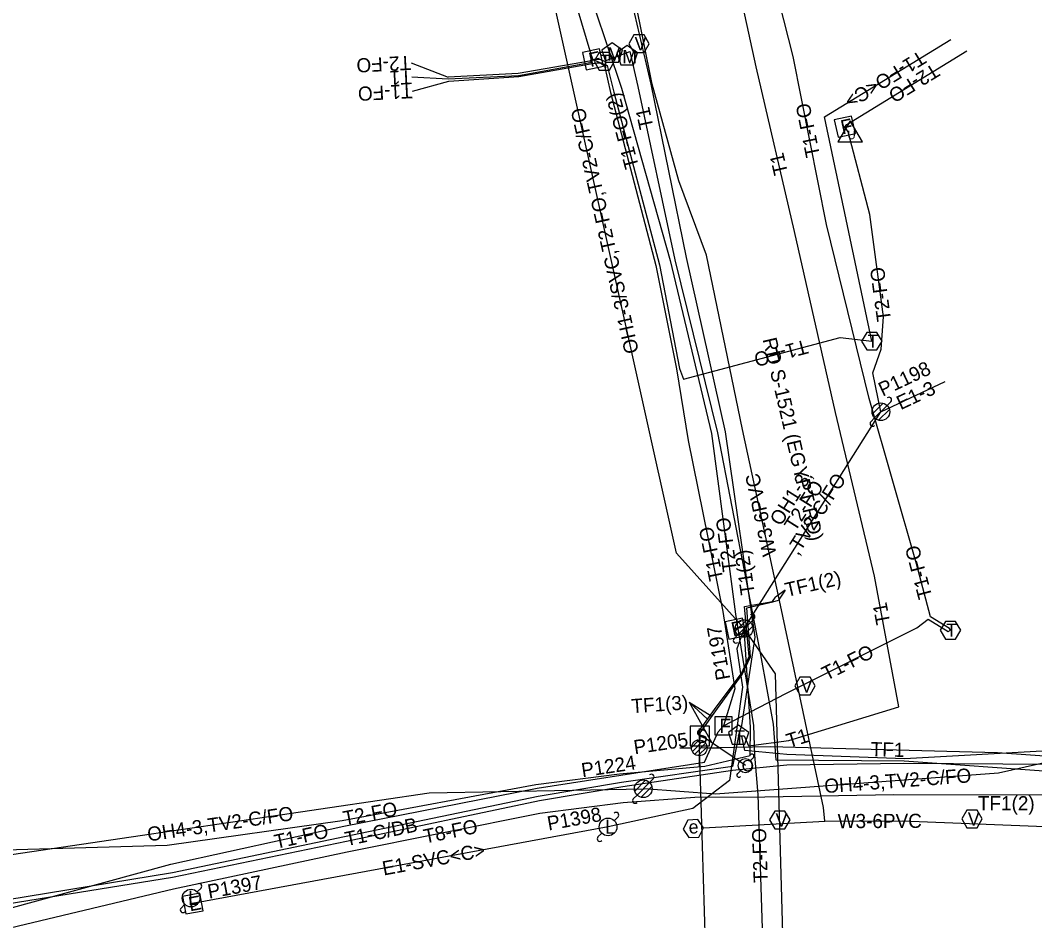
# Model space of a CAD drawing. Extents: x 2336688 to 2352634, y 362473 to 369571.
# Drawn here: x 2351896.3 to 2352182.9, y 368960.9 to 369215.5 of the extents above; entities that cross this region are included whole.
import ezdxf

# ---------------------------------------------------------------- set-up
doc = ezdxf.new("R2010")
doc.units = 0
for name, color, linetype in [('RD_EX_DV_Prop', 7, 'Continuous'), ('RD_EX_DV_TX_Prop', 7, 'Continuous'), ('RD_EX_RW', 7, 'Continuous'), ('RD_EX_RW_TX', 7, 'Continuous'), ('RD_HC_Data_Tic', 7, 'Continuous'), ('RD_PD_CstnLmt', 7, 'Continuous'), ('RD_PD_Final_TrvlWay', 7, 'Continuous'), ('RD_PD_FOC', 7, 'Continuous'), ('RD_PD_PatLn3', 7, 'Continuous'), ('RD_PD_PatLn4', 7, 'Continuous'), ('RD_SHT_ShtClip', 7, 'Continuous'), ('RD_Sketch2', 7, 'Continuous'), ('RD_Sketch8', 7, 'Continuous'), ('RD_TX_Misc1', 7, 'Continuous')]:
    doc.layers.add(name, color=color, linetype=linetype)

msp = doc.modelspace()

# ---------------------------------------------------------------- linework, layer by layer
at = {"layer": 'RD_EX_RW'}
for p, q in [((2352006.73, 369203.5), (2352017.18, 369199.37)), ((2352006.94, 369199.47), (2352017.22, 369198.89)), ((2352007.11, 369195.47), (2352017.4, 369198.31))]:
    msp.add_line(p, q, dxfattribs=at)
at = {"layer": 'RD_EX_RW_TX'}
for points in [[(2351882.96, 368961.6), (2351938.79, 368976.9), (2351987.72, 368987.57), (2352042.33, 368998.31), (2352089.62, 369005.75), (2352093.46, 369014.31), (2352094.98, 369015.98), (2352112.55, 369025.15), (2352149.58, 369043.65), (2352152.79, 369046.13), (2352158.47, 369042.65), (2352159.12, 369043.02), (2352158.82, 369043.5), (2352153.46, 369046.79), (2352149.48, 369061.78), (2352136.12, 369108.51), (2352124.11, 369157.73), (2352114.64, 369205.23), (2352102.73, 369252.4), (2352091.67, 369303.48), (2352080.48, 369361.01), (2352072.4, 369400.34), (2352061.58, 369447.94), (2352048.21, 369498.55)], [(2352099.24, 369013.18), (2352100.77, 369013.18), (2352102.01, 369010.35), (2352113.48, 369011.8), (2352144.5, 369021.33), (2352137.63, 369058.32), (2352126.61, 369104.63), (2352115.02, 369155.75), (2352104.18, 369202.36), (2352093.63, 369250.91), (2352082.32, 369302.6), (2352074.09, 369341.41), (2352079.44, 369355.35), (2352079.44, 369356.53), (2352079.15, 369355.79), (2352073.69, 369342.66), (2352070.62, 369358.43), (2352061.32, 369398.59), (2352050.18, 369444.73), (2352038.41, 369496.7)], [(2352001.58, 369492.45), (2352004.02, 369485.34), (2352012.81, 369439.77), (2352023.11, 369388.83), (2352034.68, 369342.96), (2352043.16, 369279.52), (2352050.69, 369242.38), (2352066.16, 369196.28), (2352079.88, 369147.58), (2352091.56, 369098.6), (2352098.41, 369047.57), (2352103.47, 369016.03), (2352103.73, 369007.69), (2352104.69, 368996.59), (2352107.92, 368897.46), (2352108.57, 368885.58), (2352108.45, 368884.09), (2352110.04, 368883.31), (2352120.9, 368857.81), (2352128.32, 368840.02), (2352133.08, 368783.49)], [(2352099.24, 369013.18), (2352100.17, 369016.12), (2352103.97, 369041.01), (2352095.58, 369099.08), (2352084.55, 369148.38), (2352074.51, 369197.44), (2352063.29, 369245.58), (2352050.57, 369294.92), (2352040.76, 369344.96), (2352028.6, 369392.74), (2352017.72, 369440.57), (2352010.21, 369491.1)], [(2352049.25, 369275.42), (2352042.97, 369271.71), (2352041.48, 369266.72), (2352046.93, 369241.42), (2352057.49, 369205.93), (2352058.07, 369204.44), (2352057.07, 369203.93), (2352036.99, 369200.44), (2352017.18, 369199.37)], [(2352136.89, 369124.76), (2352123.5, 369188.17), (2352159.19, 369210.05)], [(2352017.22, 369198.89), (2352037.02, 369199.92), (2352057.29, 369203.53), (2352058.07, 369204.44), (2352059.01, 369204.47), (2352060.05, 369204.49), (2352061.29, 369203.9), (2352068.47, 369206.66), (2352070.73, 369196.74), (2352081.19, 369147.72), (2352093.25, 369098.87), (2352105.47, 369036.02), (2352109, 369016.44), (2352109.72, 369006.36), (2352146.03, 369006.1), (2352188.1, 369003.03), (2352237.18, 369001.37), (2352287.91, 368997.38), (2352339.27, 368990.42)], [(2352139.44, 369104.8), (2352137.15, 369115.83), (2352139.48, 369122.53), (2352140.22, 369131.63), (2352136.29, 369160.62), (2352130.19, 369183.91), (2352129.26, 369185.4), (2352129.84, 369186.06), (2352163.76, 369206.85)], [(2352017.4, 369198.31), (2352037.11, 369199.59), (2352057.4, 369203.16), (2352059.14, 369203.44), (2352060.23, 369203.42), (2352061.37, 369202.63), (2352063.01, 369195.08), (2352075.89, 369146.17), (2352081.68, 369116.94), (2352085.01, 369096.65), (2352094.74, 369048.33), (2352098.18, 369026.42), (2352094.98, 369015.98)], [(2352058.07, 369204.44), (2352062.07, 369202.66), (2352064.02, 369195.16), (2352076.86, 369146.37), (2352082.51, 369117.02), (2352083.68, 369114.01), (2352127.97, 369125.78), (2352136.89, 369124.76)], [(2351674.66, 368979.28), (2351676.95, 368964.93), (2351681.61, 368946.8), (2351685.81, 368947.48), (2351730.37, 368956.23), (2351762.74, 368956.69), (2351770.03, 368960.75), (2351774.28, 368967.37), (2351800.15, 368972.4), (2351872.17, 368980.36), (2351937.74, 368982.19), (2351987.22, 368989.17), (2352041.91, 368999.4), (2352065.6, 369002.37), (2352089.73, 369004.61), (2352102.55, 369007.6), (2352102.58, 369015.62), (2352100.79, 369043.46)], [(2352338.07, 368997.32), (2352288.54, 369002.61), (2352238.52, 369006.32), (2352188.44, 369009.03), (2352146.1, 369006.66), (2352112.83, 369007.85), (2352101.04, 369009.02), (2352100.18, 369013.02), (2352099.24, 369013.18), (2352099.24, 369013.18), (2352097.56, 369004.44), (2352066.15, 368999.94), (2352042.65, 368996), (2351987.9, 368984.55), (2351939.24, 368974.38), (2351880.64, 368964.81), (2351835.05, 368955.54), (2351792.2, 368945.42), (2351768.45, 368940.51), (2351765.56, 368959.31), (2351765.09, 368961.33)], [(2351880.81, 368963.77), (2351939.3, 368973.2), (2351988.46, 368983.33), (2352042.97, 368994.86), (2352066.53, 368998.78), (2352097.52, 369003.45), (2352112.86, 369004.95), (2352145.97, 369005.39), (2352187.91, 369005.14), (2352236.72, 369003.16), (2352287.61, 368995.73), (2352338.92, 368988.74)], [(2351885, 368956.88), (2351939.56, 368969.89), (2351988.67, 368980.31), (2352043.04, 368991.24), (2352066.63, 368994.3), (2352086.86, 368995.79), (2352106.62, 368995.87), (2352143.1, 368996.58), (2352187.05, 368996.47), (2352234.49, 368995.02), (2352286.43, 368988.83), (2352336.53, 368982.42)]]:
    msp.add_lwpolyline(points, dxfattribs=at)
for points in [[(2352059.97, 369207.42), (2352055.09, 369206.35), (2352056.16, 369201.46), (2352061.04, 369202.54)], [(2352064.18, 369203.9), (2352062.73, 369206.4), (2352059.85, 369206.4), (2352058.4, 369203.9), (2352059.85, 369201.4), (2352062.73, 369201.4)], [(2352131.17, 369188.38), (2352126.29, 369187.3), (2352127.36, 369182.42), (2352132.24, 369183.49)], [(2352139.78, 369124.76), (2352138.34, 369127.25), (2352135.45, 369127.25), (2352134.01, 369124.76), (2352135.45, 369122.26), (2352138.34, 369122.26)], [(2352162.01, 369043.02), (2352160.56, 369045.52), (2352157.68, 369045.52), (2352156.23, 369043.02), (2352157.68, 369040.52), (2352160.56, 369040.52)], [(2352097.47, 369018.48), (2352092.48, 369018.48), (2352092.48, 369013.48), (2352097.47, 369013.48)], [(2352099.24, 369016.18), (2352096.38, 369014.11), (2352097.47, 369010.76), (2352101, 369010.76), (2352102.09, 369014.11)]]:
    msp.add_lwpolyline(points, close=True, dxfattribs=at)
at = {"layer": 'RD_HC_Data_Tic'}
for p, q in [((2352137.02, 369104.15), (2352140.09, 369107.21)), ((2352137.67, 369103.03), (2352141.21, 369106.56)), ((2352138.79, 369102.38), (2352141.85, 369105.44)), ((2352141.21, 369106.56), (2352142.27, 369107.63)), ((2352136.61, 369101.97), (2352137.67, 369103.03)), ((2352098.38, 369042.81), (2352101.44, 369045.88)), ((2352099.02, 369041.69), (2352102.56, 369045.23)), ((2352102.56, 369045.23), (2352103.62, 369046.29)), ((2352100.14, 369041.05), (2352103.21, 369044.11)), ((2352097.96, 369040.63), (2352099.02, 369041.69)), ((2352088.13, 369015.26), (2352088.13, 369011.97)), ((2352085.92, 369009.89), (2352088, 369011.97)), ((2352086.17, 369008.73), (2352089.16, 369011.72)), ((2352086.83, 369007.97), (2352089.92, 369011.06)), ((2352082.6, 369009.75), (2352085.92, 369009.75)), ((2352087.83, 369007.56), (2352090.33, 369010.06)), ((2352090.35, 369009.76), (2352093.66, 369009.77)), ((2352088.13, 369007.54), (2352088.13, 369004.26)), ((2352102.57, 369006.13), (2352103.42, 369006.98)), ((2352098.89, 369002.45), (2352099.74, 369003.3)), ((2352069.9, 368997.54), (2352072.96, 369000.6)), ((2352070.55, 368996.42), (2352074.08, 368999.96)), ((2352074.08, 368999.96), (2352075.14, 369001.02)), ((2352069.49, 368995.36), (2352070.55, 368996.42)), ((2352071.67, 368995.77), (2352074.73, 368998.84)), ((2352064.11, 368989.16), (2352065.17, 368990.22)), ((2352059.51, 368984.57), (2352060.58, 368985.63)), ((2351946.29, 368969.06), (2351947.35, 368970.12)), ((2351941.69, 368964.46), (2351942.75, 368965.52))]:
    msp.add_line(p, q, dxfattribs=at)
for centre, radius in [((2352139.44, 369104.8), 2.5), ((2352100.79, 369043.46), 2.5), ((2352088.13, 369009.76), 2.22), ((2352101.16, 369004.72), 2), ((2352072.32, 368998.19), 2.5), ((2352062.34, 368987.4), 2.5), ((2351944.52, 368967.29), 2.5)]:
    msp.add_circle(centre, radius, dxfattribs=at)
for centre, radius, start, end in [((2352141.74, 369108.16), 0.75, 315, 135), ((2352137.14, 369101.44), 0.75, 135, 315), ((2352103.09, 369046.82), 0.75, 315, 135), ((2352098.49, 369040.1), 0.75, 135, 315), ((2352102.99, 369007.4), 0.6, 315, 135), ((2352074.61, 369001.55), 0.75, 315, 135), ((2352099.32, 369002.03), 0.6, 135, 315), ((2352070.02, 368994.83), 0.75, 135, 315), ((2352064.64, 368990.75), 0.75, 315, 135), ((2352060.04, 368984.04), 0.75, 135, 315), ((2351946.82, 368970.65), 0.75, 315, 135), ((2351942.22, 368963.93), 0.75, 135, 315)]:
    msp.add_arc(centre, radius, start, end, dxfattribs=at)
at = {"layer": 'RD_PD_Final_TrvlWay'}
msp.add_line((2352139.44, 369104.8), (2352157.64, 369113.37), dxfattribs=at)
for points in [[(2352100.32, 369046.4), (2352095.43, 369045.36), (2352096.47, 369040.47), (2352101.36, 369041.51)], [(2351947.05, 368968.62), (2351942.13, 368967.7), (2351943.05, 368962.79), (2351947.96, 368963.7)]]:
    msp.add_lwpolyline(points, close=True, dxfattribs=at)
msp.add_lwpolyline([(2352100.79, 369043.46), (2352098.76, 369037.79), (2352100.3, 369026.92), (2352096.63, 369000.48), (2352086.32, 368992.56), (2352062.34, 368987.4), (2351945.05, 368965.7)], dxfattribs=at)
at = {"layer": 'RD_PD_FOC'}
for p, q in [((2352112.39, 369054.34), (2352109.63, 369052.37)), ((2352112.39, 369054.34), (2352110.47, 369051.52)), ((2352085.28, 369022.65), (2352091.72, 369018.74)), ((2352085.32, 369022.65), (2352090.49, 369017.87)), ((2352085.32, 369022.65), (2352091.71, 369011.16))]:
    msp.add_line(p, q, dxfattribs=at)
at = {"layer": 'RD_PD_PatLn3'}
msp.add_lwpolyline([(2352130.78, 369187.08), (2352127.31, 369181.08), (2352134.24, 369181.08)], close=True, dxfattribs=at)
at = {"layer": 'RD_SHT_ShtClip'}
for p, q in [((2352100.79, 369043.46), (2352139.44, 369104.8)), ((2352088.13, 369009.76), (2352091.68, 368889.02))]:
    msp.add_line(p, q, dxfattribs=at)
for points in [[(2352100.79, 369043.46), (2352081.67, 369064.82), (2352040.97, 369247.97), (2352049.25, 369275.42)], [(2352105.46, 368877.27), (2352113.61, 368890.51), (2352109.66, 369030.71), (2352100.79, 369043.46)], [(2352088.13, 369009.76), (2352108.15, 369010.14), (2352172.41, 369008.48), (2352192.38, 369007.05)], [(2352192.38, 369007.05), (2352172.65, 369002.58), (2352092.75, 368996.67), (2352072.58, 368998.19)], [(2351827.12, 368962.06), (2351885.36, 368978.36), (2352011.84, 368996.99), (2352072.58, 368998.19)]]:
    msp.add_lwpolyline(points, dxfattribs=at)
at = {"layer": 'RD_Sketch2'}
for points in [[(2352123.62, 368989.01), (2352123.23, 368992.87), (2352110.76, 369051.44), (2352100.32, 369099.76), (2352090.2, 369149.12), (2352082.32, 369170.12), (2352074.84, 369197.41), (2352065.04, 369246.15), (2352055.85, 369297.1), (2352046.45, 369347.59), (2352034.9, 369396.24), (2352024.46, 369441.79), (2352013.71, 369492.08)], [(2352089.34, 368987.1), (2352123.62, 368989.01), (2352145.53, 368989.09), (2352188.15, 368987.39), (2352297.48, 368978.27), (2352333.69, 368973.72)]]:
    msp.add_lwpolyline(points, dxfattribs=at)
for points in [[(2352073.96, 369208.86), (2352072.52, 369211.36), (2352069.63, 369211.36), (2352068.19, 369208.86), (2352069.63, 369206.36), (2352072.52, 369206.36)], [(2352063.51, 369209.13), (2352060.61, 369207.02), (2352061.72, 369203.61), (2352065.3, 369203.61), (2352066.41, 369207.02)], [(2352067.74, 369208.38), (2352064.84, 369206.27), (2352065.94, 369202.86), (2352069.53, 369202.86), (2352070.64, 369206.27)], [(2352120.89, 369027.26), (2352119.45, 369029.76), (2352116.56, 369029.76), (2352115.12, 369027.26), (2352116.56, 369024.76), (2352119.45, 369024.76)], [(2352113.78, 368989.37), (2352112.34, 368991.87), (2352109.45, 368991.87), (2352108.01, 368989.37), (2352109.45, 368986.87), (2352112.34, 368986.87)], [(2352168.1, 368989.67), (2352166.65, 368992.16), (2352163.77, 368992.16), (2352162.32, 368989.67), (2352163.77, 368987.17), (2352166.65, 368987.17)], [(2352089.34, 368987.1), (2352087.76, 368989.51), (2352084.88, 368989.35), (2352083.57, 368986.78), (2352085.15, 368984.36), (2352088.04, 368984.52)]]:
    msp.add_lwpolyline(points, close=True, dxfattribs=at)
at = {"layer": 'RD_Sketch8'}
for points in [[(2352088.26, 369013.09), (2352087.7, 369014.04), (2352092.95, 369021.26), (2352100.05, 369030.8), (2352102.26, 369035.59), (2352100.9, 369049.69), (2352108.83, 369051.13), (2352109.63, 369052.37)], [(2352088.26, 369013.09), (2352088.34, 369014), (2352093.25, 369020.88), (2352100.25, 369030.48), (2352102.56, 369035.46), (2352101.54, 369049.34), (2352108.92, 369051.03), (2352110.47, 369051.52)], [(2352101.16, 369004.72), (2352089.93, 369012.37), (2352088.26, 369013.09), (2352088.13, 369009.76)]]:
    msp.add_lwpolyline(points, dxfattribs=at)
msp.add_lwpolyline([(2352091.01, 369015.84), (2352085.51, 369015.84), (2352085.51, 369010.34), (2352091.01, 369010.34)], close=True, dxfattribs=at)

# ---------------------------------------------------------------- texts
at = {"layer": 'RD_EX_DV_Prop'}
for s, rotation, p in [('E1-3', 25.2073, (2352145.05, 369105.23)), ('E1-SVC<C>', 10.4808, (2351998.96, 368973.64))]:
    msp.add_text(s, height=4, rotation=rotation, dxfattribs=at).set_placement(p)
at = {"layer": 'RD_EX_DV_TX_Prop'}
for s, rotation, p in [('P1198', 25.2073, (2352139.95, 369109.04)), ('P1197', 100.2691, (2352096.92, 369029.29)), ('P1205', 8.4903, (2352069.91, 369007.92)), ('P1224', 8.4903, (2352055.12, 369001.42)), ('P1398', 10.334, (2352045.56, 368986.36)), ('P1397', 10.334, (2351949.6, 368967.1))]:
    msp.add_text(s, height=4, rotation=rotation, dxfattribs=at).set_placement(p)
at = {"layer": 'RD_EX_RW'}
for s, rotation, p in [('T2-FO', 182.9806, (2352006.59, 369205.49)), ('T1-FO<C>', 211.5101, (2352150.54, 369207.09)), ('T2-FO', 211.5101, (2352154.35, 369203.43)), ('T1', 182.9806, (2352006.8, 369201.46)), ('T1-FO', 182.9806, (2352007.01, 369197.47)), ('T1-FO(2)', 104.7497, (2352071.13, 369174.07)), ('T1-FO', 101.2742, (2352122.27, 369177.19)), ('T1', 102.0514, (2352075.24, 369185.15)), ('T1', 103.104, (2352113.24, 369172.25)), ('T2-FO', 97.7071, (2352142.37, 369130.62)), ('T1-FO', 194.8851, (2352118.19, 369125.25)), ('T2-FO', 97.6435, (2352098.78, 369059.82)), ('T1-FO', 101.3845, (2352094.94, 369057.43)), ('T1(2)', 98.2279, (2352103.85, 369053.33)), ('T1-FO', 104.8776, (2352154.03, 369052.44)), ('T1', 100.5082, (2352142.14, 369045)), ('T1-FO', 26.5514, (2352124.04, 369028.66)), ('T1', 17.0661, (2352113.44, 369009.7)), ('T2-FO', 10.5973, (2351987.89, 368987.82)), ('T1-FO', 12.3017, (2351968.54, 368981.17)), ('T1-C/DB', 11.8142, (2351988.44, 368981.94)), ('T8-FO', 11.3699, (2352010.64, 368982.69)), ('T2-FO', 91.8685, (2352107.5, 368971.68))]:
    msp.add_text(s, height=4, rotation=rotation, dxfattribs=at).set_placement(p)
at = {"layer": 'RD_EX_RW_TX'}
for p in [(2352057.39, 369202.25), (2352128.58, 369183.2)]:
    msp.add_text('F', height=4, rotation=12.3683, dxfattribs=at).set_placement(p)
for s, height, p in [('T', 3.75, (2352060.08, 369202.02)), ('T', 3.75, (2352135.68, 369122.88)), ('T', 3.75, (2352157.91, 369041.15)), ('F', 4, (2352093.84, 369013.98)), ('T', 3.75, (2352098.01, 369010.96))]:
    msp.add_text(s, height=height, dxfattribs=at).set_placement(p)
at = {"layer": 'RD_HC_Data_Tic'}
msp.add_text('O', height=3.2, dxfattribs=at).set_placement((2352100.12, 369003.12))
for p in [(2352061.53, 368985.46), (2351943.71, 368965.35)]:
    msp.add_text('L', height=4, rotation=360, dxfattribs=at).set_placement(p)
at = {"layer": 'RD_PD_CstnLmt'}
for rotation, p in [(102.1941, (2352110, 369064.42)), (0.2145, (2352127.25, 368987.03))]:
    msp.add_text('W3-6PVC', height=4, rotation=rotation, dxfattribs=at).set_placement(p)
at = {"layer": 'RD_PD_Final_TrvlWay'}
for rotation, p in [(12.0621, (2352097.63, 369041.23)), (10.572, (2351944.22, 368963.51))]:
    msp.add_text('E', height=4, rotation=rotation, dxfattribs=at).set_placement(p)
at = {"layer": 'RD_PD_FOC'}
for s, rotation, p in [('TF1(2)', 12.8817, (2352112.88, 369052.4)), ('TF1(3)', 3.8761, (2352069.1, 369019.55)), ('TF1(2)', 359.8566, (2352166.86, 368992.12))]:
    msp.add_text(s, height=4, rotation=rotation, dxfattribs=at).set_placement(p)
at = {"layer": 'RD_PD_PatLn3'}
msp.add_text('U', height=2.4, dxfattribs=at).set_placement((2352130.02, 369181.88))
at = {"layer": 'RD_PD_PatLn4'}
for s, rotation, p in [('OH1-3/SVC,T2-FO,TV2-C/FO', 102.5271, (2352071.08, 369121.71)), ('OH1-3,', 57.7844, (2352111.17, 369072.25)), ('T2-FO', 57.7844, (2352115.25, 369070.68)), (',TV2-C/FO', 57.7844, (2352116.03, 369063.9)), ('TF1', 358.5142, (2352136.53, 369007.41)), ('OH4-3,TV2-C/FO', 4.2533, (2352123.61, 368996.94)), ('OH4-3,TV2-C/FO', 8.3827, (2351932.47, 368983.27))]:
    msp.add_text(s, height=4, rotation=rotation, dxfattribs=at).set_placement(p)
at = {"layer": 'RD_Sketch2'}
for s, p in [('V', (2352069.86, 369206.99)), ('M', (2352062.14, 369204.09)), ('M', (2352066.37, 369203.34)), ('V', (2352116.8, 369025.39)), ('V', (2352109.68, 368987.49)), ('V', (2352164, 368987.79))]:
    msp.add_text(s, height=3.75, dxfattribs=at).set_placement(p)
msp.add_text('e', height=3.75, rotation=3.1957, dxfattribs=at).set_placement((2352085.22, 368985.46))
at = {"layer": 'RD_Sketch8'}
msp.add_text('S', height=3.89, dxfattribs=at).set_placement((2352087.07, 369011.14))
at = {"layer": 'RD_TX_Misc1'}
msp.add_text('RD S-1521 (EGYPT RD)', height=4, rotation=283.1889, dxfattribs=at).set_placement((2352105.99, 369125.27))

doc.saveas('drawing.dxf')
